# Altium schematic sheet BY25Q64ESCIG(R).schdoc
size 127 x 101 mm
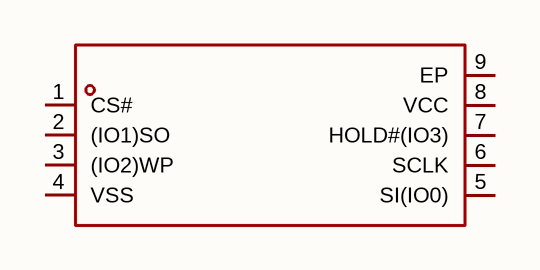
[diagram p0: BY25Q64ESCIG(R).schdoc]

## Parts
U?  by25q64escig(r)  [DFN-8_L3.0-W2.0-P0.50-BL-EP-3]  (value not drawn)

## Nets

Not connected (* = marked no-connect by the designer): U? 1(CS#) 2((IO1)SO) 3((IO2)WP) 4(VSS) 5(SI(IO0)) 6(SCLK) 7(HOLD#(IO3)) 8(VCC) 9(EP)

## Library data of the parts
U? = by25q64escig(r): 接口类型:SPI;存储容量:64Mbit;时钟频率(fc):120MHz;; Manufacturer: BOYAMICRO(博雅); AddInBom: yes; ModelId: 681fc3fc48ac4e78866afc9c9a96fa6a; ModelTransform: 79.527,118.8974,0,0,0,0,0,0,0; Interface: SPI; Memory Size: 64Mbit; Clock Frequency: 120MHz; Voltage - Supply: 2.7V~3.6V; Standby Supply Current: 0.7uA; Program / Erase Cycles: 100000次; Page Programming Time (Tpp): 450us; Block Erase Time(tBE): 180ms@(64KB); Data Retention - TDR (Year): 20年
